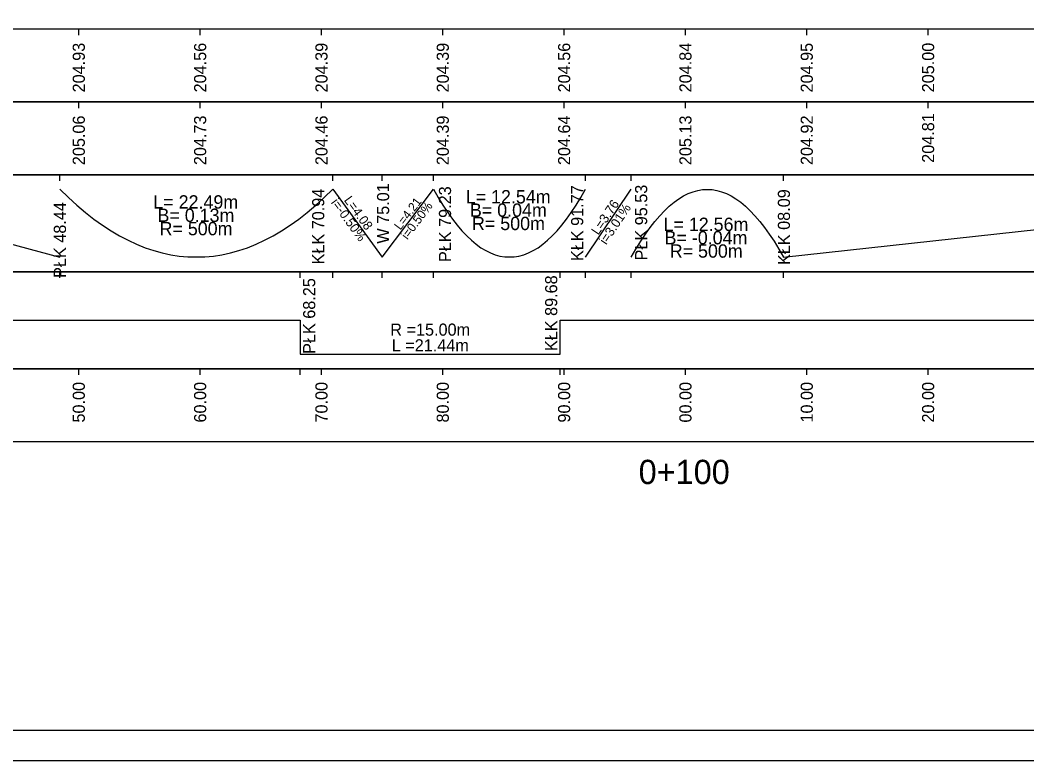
# Model space of a CAD drawing. Extents: x 6512707 to 6513007, y 6022307 to 6022469.
# Drawn here: x 6512789.6 to 6512872.6, y 6022306.7 to 6022367.8 of the extents above; entities that cross this region are included whole.
import ezdxf

# ---------------------------------------------------------------- set-up
doc = ezdxf.new("R2010")
doc.units = 0
for name, color, linetype in [('1', 7, 'Continuous'), ('31', 7, 'Continuous'), ('42', 7, 'Continuous'), ('54', 7, 'Continuous'), ('Level 20', 7, 'Continuous'), ('maxp_ramka_2', 7, 'Continuous')]:
    doc.layers.add(name, color=color, linetype=linetype)

msp = doc.modelspace()

# ---------------------------------------------------------------- linework, layer by layer
for points in [[(6512772.058, 6022353.862), (6512792.862, 6022348.262)], [(6512792.862, 6022353.862), (6512793.565, 6022353.184), (6512794.268, 6022352.549), (6512794.971, 6022351.959), (6512795.674, 6022351.412), (6512796.377, 6022350.909), (6512797.08, 6022350.449), (6512797.783, 6022350.034), (6512798.486, 6022349.662), (6512799.189, 6022349.334), (6512799.891, 6022349.049), (6512800.594, 6022348.809), (6512801.297, 6022348.612), (6512802, 6022348.459), (6512802.703, 6022348.349), (6512803.406, 6022348.284), (6512804.812, 6022348.284), (6512805.515, 6022348.349), (6512806.218, 6022348.459), (6512806.921, 6022348.612), (6512807.624, 6022348.809), (6512808.327, 6022349.049), (6512809.03, 6022349.334), (6512809.733, 6022349.662), (6512810.436, 6022350.034), (6512811.139, 6022350.449), (6512811.841, 6022350.909), (6512812.544, 6022351.412), (6512813.247, 6022351.959), (6512813.95, 6022352.549), (6512814.653, 6022353.184), (6512815.356, 6022353.862)], [(6512815.356, 6022353.862), (6512819.433, 6022348.262)], [(6512819.433, 6022348.262), (6512823.647, 6022353.862)], [(6512823.647, 6022353.862), (6512824.039, 6022353.184), (6512824.431, 6022352.549), (6512824.823, 6022351.959), (6512825.215, 6022351.412), (6512825.607, 6022350.909), (6512825.998, 6022350.449), (6512826.39, 6022350.034), (6512826.782, 6022349.662), (6512827.174, 6022349.334), (6512827.566, 6022349.049), (6512827.958, 6022348.809), (6512828.35, 6022348.612), (6512828.742, 6022348.459), (6512829.134, 6022348.349), (6512829.526, 6022348.284), (6512830.31, 6022348.284), (6512830.702, 6022348.349), (6512831.094, 6022348.459), (6512831.486, 6022348.612), (6512831.877, 6022348.809), (6512832.269, 6022349.049), (6512832.661, 6022349.334), (6512833.053, 6022349.662), (6512833.445, 6022350.034), (6512833.837, 6022350.449), (6512834.229, 6022350.909), (6512834.621, 6022351.412), (6512835.013, 6022351.959), (6512835.405, 6022352.549), (6512835.797, 6022353.184), (6512836.189, 6022353.862)], [(6512836.189, 6022348.262), (6512839.946, 6022353.862)], [(6512839.946, 6022348.262), (6512840.338, 6022348.94), (6512840.731, 6022349.574), (6512841.123, 6022350.165), (6512841.516, 6022350.712), (6512841.908, 6022351.215), (6512842.301, 6022351.674), (6512842.693, 6022352.09), (6512843.086, 6022352.462), (6512843.478, 6022352.79), (6512843.871, 6022353.074), (6512844.263, 6022353.315), (6512844.656, 6022353.512), (6512845.048, 6022353.665), (6512845.44, 6022353.774), (6512845.833, 6022353.84), (6512846.618, 6022353.84), (6512847.01, 6022353.774), (6512847.403, 6022353.665), (6512847.795, 6022353.512), (6512848.188, 6022353.315), (6512848.58, 6022353.074), (6512848.973, 6022352.79), (6512849.365, 6022352.462), (6512849.758, 6022352.09), (6512850.15, 6022351.674), (6512850.543, 6022351.215), (6512850.935, 6022350.712), (6512851.328, 6022350.165), (6512851.72, 6022349.574), (6512852.113, 6022348.94), (6512852.505, 6022348.262)], [(6512852.505, 6022348.262), (6512903.729, 6022353.862)], [(6512744.419, 6022343.062), (6512760.648, 6022343.062), (6512760.648, 6022340.262), (6512762.864, 6022340.262), (6512762.864, 6022343.062), (6512778.8, 6022343.062), (6512778.8, 6022345.862), (6512784.027, 6022345.862), (6512784.027, 6022343.062), (6512812.664, 6022343.062), (6512812.664, 6022340.262), (6512834.104, 6022340.262), (6512834.104, 6022343.062), (6512900.391, 6022343.062), (6512900.391, 6022340.262), (6512925.117, 6022340.262), (6512925.117, 6022343.062), (6512943.179, 6022343.062), (6512943.179, 6022343.062), (6512944.849, 6022343.062), (6512944.849, 6022343.062), (6512949.827, 6022343.062)]]:
    msp.add_lwpolyline(points)
at = {"layer": '54'}
for points in [[(6512744.419, 6022361.062), (6512954.419, 6022361.062), (6512954.419, 6022367.062), (6512744.419, 6022367.062)], [(6512744.419, 6022355.062), (6512954.419, 6022355.062), (6512954.419, 6022361.062), (6512744.419, 6022361.062)], [(6512744.419, 6022347.062), (6512954.419, 6022347.062), (6512954.419, 6022355.062), (6512744.419, 6022355.062)], [(6512744.419, 6022339.062), (6512954.419, 6022339.062), (6512954.419, 6022347.062), (6512744.419, 6022347.062)], [(6512744.419, 6022333.062), (6512954.419, 6022333.062), (6512954.419, 6022339.062), (6512744.419, 6022339.062)]]:
    msp.add_lwpolyline(points, close=True, dxfattribs=at)
for points in [[(6512794.419, 6022366.562), (6512794.419, 6022367.062)], [(6512804.419, 6022366.562), (6512804.419, 6022367.062)], [(6512814.419, 6022366.562), (6512814.419, 6022367.062)], [(6512824.419, 6022366.562), (6512824.419, 6022367.062)], [(6512834.419, 6022366.562), (6512834.419, 6022367.062)], [(6512844.419, 6022366.562), (6512844.419, 6022367.062)], [(6512854.419, 6022366.562), (6512854.419, 6022367.062)], [(6512864.419, 6022366.562), (6512864.419, 6022367.062)], [(6512794.419, 6022360.562), (6512794.419, 6022361.062)], [(6512804.419, 6022360.562), (6512804.419, 6022361.062)], [(6512814.419, 6022360.562), (6512814.419, 6022361.062)], [(6512824.419, 6022360.562), (6512824.419, 6022361.062)], [(6512834.419, 6022360.562), (6512834.419, 6022361.062)], [(6512844.419, 6022360.562), (6512844.419, 6022361.062)], [(6512854.419, 6022360.562), (6512854.419, 6022361.062)], [(6512864.419, 6022360.562), (6512864.419, 6022361.062)], [(6512792.862, 6022354.562), (6512792.862, 6022355.062)], [(6512815.356, 6022354.562), (6512815.356, 6022355.062)], [(6512819.433, 6022354.562), (6512819.433, 6022355.062)], [(6512823.647, 6022354.562), (6512823.647, 6022355.062)], [(6512836.189, 6022354.562), (6512836.189, 6022355.062)], [(6512839.946, 6022354.562), (6512839.946, 6022355.062)], [(6512852.505, 6022354.562), (6512852.505, 6022355.062)], [(6512792.862, 6022346.562), (6512792.862, 6022347.062)], [(6512812.664, 6022346.562), (6512812.664, 6022347.062)], [(6512815.356, 6022346.562), (6512815.356, 6022347.062)], [(6512819.433, 6022346.562), (6512819.433, 6022347.062)], [(6512823.647, 6022346.562), (6512823.647, 6022347.062)], [(6512834.104, 6022346.562), (6512834.104, 6022347.062)], [(6512836.189, 6022346.562), (6512836.189, 6022347.062)], [(6512839.946, 6022346.562), (6512839.946, 6022347.062)], [(6512852.505, 6022346.562), (6512852.505, 6022347.062)], [(6512794.419, 6022338.562), (6512794.419, 6022339.062)], [(6512804.419, 6022338.562), (6512804.419, 6022339.062)], [(6512812.664, 6022338.562), (6512812.664, 6022339.062)], [(6512814.419, 6022338.562), (6512814.419, 6022339.062)], [(6512824.419, 6022338.562), (6512824.419, 6022339.062)], [(6512834.104, 6022338.562), (6512834.104, 6022339.062)], [(6512834.419, 6022338.562), (6512834.419, 6022339.062)], [(6512844.419, 6022338.562), (6512844.419, 6022339.062)], [(6512854.419, 6022338.562), (6512854.419, 6022339.062)], [(6512864.419, 6022338.562), (6512864.419, 6022339.062)]]:
    msp.add_lwpolyline(points, dxfattribs=at)
at = {"layer": 'maxp_ramka_2'}
for points in [[(6512706.616, 6022455.239), (6513006.616, 6022455.239), (6513006.616, 6022306.739), (6512706.616, 6022306.739)], [(6512719.116, 6022309.239), (6512719.116, 6022452.739), (6513004.116, 6022452.739), (6513004.116, 6022309.239)]]:
    msp.add_lwpolyline(points, close=True, dxfattribs=at)

# ---------------------------------------------------------------- texts
at = {"layer": '1'}
for s, p in [('205.06', (6512794.919, 6022355.854)), ('204.73', (6512804.919, 6022355.854)), ('204.46', (6512814.919, 6022355.854)), ('204.39', (6512824.919, 6022355.852)), ('204.64', (6512834.919, 6022355.858)), ('205.13', (6512844.919, 6022355.854)), ('204.92', (6512854.919, 6022355.864)), ('204.81', (6512864.919, 6022356.047)), ('KŁK 70.94', (6512814.653, 6022347.667)), ('W 75.01', (6512819.999, 6022349.382)), ('PŁK 79.23', (6512825.103, 6022347.865)), ('KŁK 91.77', (6512835.997, 6022347.947)), ('PŁK 95.53', (6512841.271, 6022347.996)), ('KŁK 08.09', (6512853.036, 6022347.622)), ('PŁK 48.44', (6512793.362, 6022346.562))]:
    msp.add_text(s, height=1, rotation=90, dxfattribs=at).set_placement(p)
msp.add_text('0+100', height=2, dxfattribs=at).set_placement((6512840.564, 6022329.562))
at = {"layer": '31'}
for s, p in [('204.93', (6512794.919, 6022361.854)), ('204.56', (6512804.919, 6022361.854)), ('204.39', (6512814.919, 6022361.852)), ('204.39', (6512824.919, 6022361.852)), ('204.56', (6512834.919, 6022361.854)), ('204.84', (6512844.919, 6022361.858)), ('204.95', (6512854.919, 6022361.846)), ('205.00', (6512864.919, 6022361.858))]:
    msp.add_text(s, height=1, rotation=90, dxfattribs=at).set_placement(p)
at = {"layer": '42'}
for s, p in [('L= 12.54m', (6512826.316, 6022352.699)), ('L= 22.49m', (6512800.566, 6022352.273)), ('B= 0.13m', (6512800.907, 6022351.173)), ('B= 0.04m', (6512826.658, 6022351.599)), ('R= 500m', (6512801.078, 6022350.073)), ('R= 500m', (6512826.829, 6022350.499)), ('L= 12.56m', (6512842.615, 6022350.426)), ('B= -0.04m', (6512842.701, 6022349.326)), ('R= 500m', (6512843.128, 6022348.226))]:
    msp.add_text(s, height=1.1, dxfattribs=at).set_placement(p)
at = {"layer": '54'}
for s, p in [('PŁK 68.25', (6512813.908, 6022340.293)), ('KŁK 89.68', (6512833.854, 6022340.524)), ('50.00', (6512794.919, 6022334.634)), ('60.00', (6512804.919, 6022334.634)), ('70.00', (6512814.919, 6022334.634)), ('80.00', (6512824.919, 6022334.634)), ('90.00', (6512834.919, 6022334.634)), ('00.00', (6512844.919, 6022334.634)), ('10.00', (6512854.919, 6022334.634)), ('20.00', (6512864.919, 6022334.634))]:
    msp.add_text(s, height=1, rotation=90, dxfattribs=at).set_placement(p)
for s, p in [('R =15.00m', (6512820.093, 6022341.794)), ('L =21.44m', (6512820.209, 6022340.5))]:
    msp.add_text(s, height=1, dxfattribs=at).set_placement(p)
at = {"layer": 'Level 20'}
for s, height, rotation, p in [('i=-0.50%', 0.7615, 306.05595, (6512815.168, 6022352.763)), ('L=4.08', 0.7615, 306.05595, (6512816.243, 6022352.962)), ('L=4.21', 0.7255, 53.0408, (6512820.924, 6022350.453)), ('L=3.76', 0.7669, 56.14231, (6512837.235, 6022350.041)), ('i=0.50%', 0.7255, 53.0408, (6512821.505, 6022349.663)), ('i=3.01%', 0.7669, 56.14231, (6512837.893, 6022349.241))]:
    msp.add_text(s, height=height, rotation=rotation, dxfattribs=at).set_placement(p)

doc.saveas('drawing.dxf')
